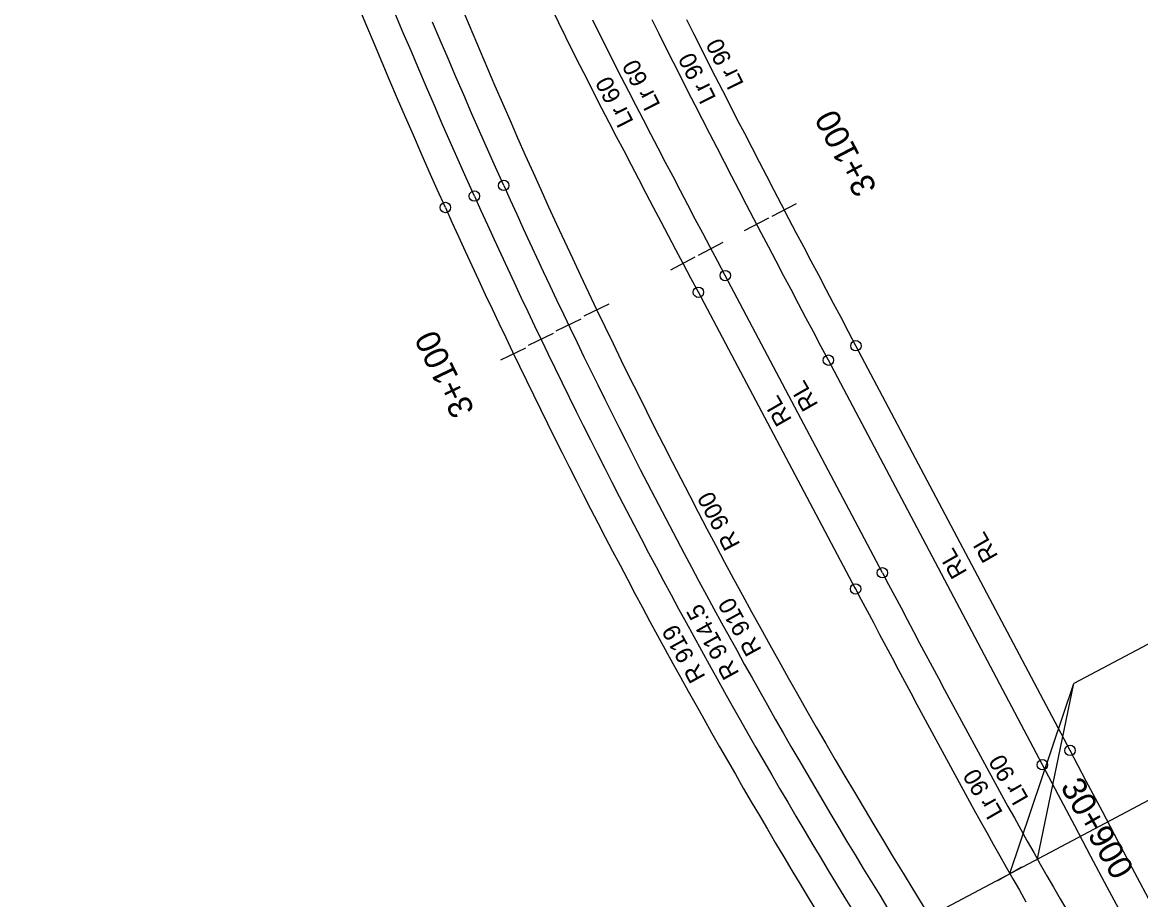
# Model space of a CAD drawing. Extents: x 149855 to 151460, y 6580726 to 6583068.
# Drawn here: x 150982.7 to 151144.3, y 6581306.4 to 6581433.2 of the extents above; entities that cross this region are included whole.
import ezdxf

# ---------------------------------------------------------------- set-up
doc = ezdxf.new("R2010")
doc.units = 0
for name, color, linetype in [('Hektometer L', 7, 'Continuous'), ('Hektometer T', 7, 'Continuous'), ('Konnektion längdmätning L', 7, 'Continuous'), ('Spårgeometri T', 7, 'Continuous'), ('Spårmitt L', 7, 'Continuous'), ('Tp bef behålls P', 7, 'Continuous')]:
    doc.layers.add(name, color=color, linetype=linetype)

msp = doc.modelspace()

# ---------------------------------------------------------------- linework, layer by layer
at = {"layer": 'Hektometer L'}
for points in [[(151091.04, 6581405.14), (151094.59, 6581406.99)], [(151087.05, 6581403.07), (151090.6, 6581404.92)], [(151080.44, 6581399.55), (151083.98, 6581401.42)], [(151076.42, 6581397.42), (151079.96, 6581399.29)], [(151063.91, 6581390.78), (151067.52, 6581392.51)], [(151059.84, 6581388.61), (151063.45, 6581390.35)], [(151055.85, 6581386.55), (151059.46, 6581388.28)], [(151051.88, 6581384.42), (151055.49, 6581386.15)], [(151123.66, 6581309.21), (151127.14, 6581311.18)]]:
    msp.add_lwpolyline(points, dxfattribs=at)
at = {"layer": 'Konnektion längdmätning L'}
for p, q in [((150982.75, 6581234.65), (151228.43, 6581364.77)), ((151125.39, 6581310.2), (151134.66, 6581337.65)), ((151129.38, 6581312.32), (151134.66, 6581337.65))]:
    msp.add_line(p, q, dxfattribs=at)
msp.add_lwpolyline([(151223.03, 6581384.46), (151134.66, 6581337.65)], dxfattribs=at)
at = {"layer": 'Spårmitt L'}
for points in [[(151043.85, 6581406.41), (151042.69, 6581409.01), (151041.53, 6581411.62), (151040.37, 6581414.24), (151039.23, 6581416.85), (151038.09, 6581419.48), (151036.95, 6581422.1), (151035.83, 6581424.72), (151034.71, 6581427.35), (151033.6, 6581429.98), (151032.49, 6581432.62), (151031.38, 6581435.25)], [(151048.04, 6581408.07), (151046.87, 6581410.68), (151045.71, 6581413.29), (151044.56, 6581415.91), (151043.41, 6581418.52), (151042.27, 6581421.14), (151041.14, 6581423.77), (151040.01, 6581426.39), (151038.89, 6581429.02), (151037.78, 6581431.65), (151036.67, 6581434.28)], [(151080.41, 6581394.16), (151079.33, 6581396.2), (151078.25, 6581398.24), (151077.17, 6581400.28), (151076.09, 6581402.32), (151075.02, 6581404.36), (151073.94, 6581406.4), (151072.87, 6581408.44), (151071.79, 6581410.48), (151070.72, 6581412.53), (151069.66, 6581414.58), (151068.59, 6581416.62), (151067.53, 6581418.67), (151066.48, 6581420.72), (151065.42, 6581422.78), (151064.38, 6581424.83), (151063.33, 6581426.89), (151062.29, 6581428.95), (151061.26, 6581431.02), (151060.23, 6581433.08), (151059.21, 6581435.15)], [(151052.28, 6581409.61), (151051.11, 6581412.22), (151049.95, 6581414.83), (151048.79, 6581417.44), (151047.64, 6581420.06), (151046.5, 6581422.68), (151045.37, 6581425.3), (151044.25, 6581427.93), (151043.12, 6581430.56), (151042.01, 6581433.19)], [(151084.28, 6581396.58), (151083.2, 6581398.62), (151082.12, 6581400.66), (151081.04, 6581402.7), (151079.96, 6581404.74), (151078.89, 6581406.78), (151077.81, 6581408.83), (151076.74, 6581410.87), (151075.67, 6581412.91), (151074.6, 6581414.96), (151073.53, 6581417.01), (151072.47, 6581419.05), (151071.41, 6581421.1), (151070.36, 6581423.16), (151069.3, 6581425.21), (151068.26, 6581427.27), (151067.21, 6581429.33), (151066.18, 6581431.39), (151065.14, 6581433.45)], [(151099.18, 6581384.36), (151098.1, 6581386.4), (151097.02, 6581388.44), (151095.94, 6581390.48), (151094.86, 6581392.52), (151093.79, 6581394.56), (151092.71, 6581396.6), (151091.63, 6581398.64), (151090.56, 6581400.69), (151089.49, 6581402.73), (151088.42, 6581404.77), (151087.35, 6581406.82), (151086.28, 6581408.87), (151085.22, 6581410.91), (151084.16, 6581412.96), (151083.1, 6581415.01), (151082.04, 6581417.06), (151080.99, 6581419.12), (151079.94, 6581421.17), (151078.89, 6581423.23), (151077.85, 6581425.29), (151076.81, 6581427.35), (151075.77, 6581429.41), (151074.74, 6581431.48), (151073.72, 6581433.54)], [(151103.17, 6581386.42), (151102.09, 6581388.46), (151101.01, 6581390.5), (151099.93, 6581392.54), (151098.86, 6581394.58), (151097.78, 6581396.62), (151096.7, 6581398.66), (151095.63, 6581400.71), (151094.55, 6581402.75), (151093.48, 6581404.79), (151092.41, 6581406.84), (151091.34, 6581408.88), (151090.27, 6581410.93), (151089.21, 6581412.98), (151088.15, 6581415.03), (151087.09, 6581417.08), (151086.03, 6581419.13), (151084.98, 6581421.18), (151083.93, 6581423.24), (151082.88, 6581425.29), (151081.84, 6581427.35), (151080.8, 6581429.41), (151079.77, 6581431.48), (151078.74, 6581433.54)], [(151106.99, 6581353.65), (151084.28, 6581396.58)], [(151103.11, 6581351.31), (151080.41, 6581394.16)], [(151134.09, 6581327.99), (151103.17, 6581386.42)], [(151130.1, 6581325.93), (151099.18, 6581384.36)], [(151106.99, 6581353.65), (151107.89, 6581351.96), (151108.79, 6581350.26), (151109.68, 6581348.57), (151110.58, 6581346.88), (151111.48, 6581345.19), (151112.37, 6581343.5), (151113.27, 6581341.81), (151114.17, 6581340.12), (151115.08, 6581338.43), (151115.98, 6581336.74), (151116.88, 6581335.05), (151117.79, 6581333.36), (151118.7, 6581331.68), (151119.61, 6581329.99), (151120.52, 6581328.31), (151121.44, 6581326.63), (151122.35, 6581324.95), (151123.27, 6581323.27), (151124.2, 6581321.59), (151125.12, 6581319.91), (151126.05, 6581318.24), (151126.98, 6581316.57), (151127.92, 6581314.9), (151128.86, 6581313.23), (151129.8, 6581311.56), (151130.75, 6581309.9), (151131.7, 6581308.24), (151132.66, 6581306.58), (151133.62, 6581304.92)], [(151102.99, 6581351.53), (151103.89, 6581349.84), (151104.78, 6581348.14), (151105.68, 6581346.45), (151106.58, 6581344.76), (151107.48, 6581343.07), (151108.38, 6581341.38), (151109.28, 6581339.69), (151110.18, 6581338), (151111.08, 6581336.31), (151111.98, 6581334.62), (151112.89, 6581332.93), (151113.8, 6581331.25), (151114.7, 6581329.56), (151115.62, 6581327.88), (151116.53, 6581326.19), (151117.44, 6581324.51), (151118.36, 6581322.83), (151119.28, 6581321.15), (151120.21, 6581319.48), (151121.13, 6581317.8), (151122.06, 6581316.13), (151123, 6581314.45), (151123.93, 6581312.78), (151124.87, 6581311.12), (151125.82, 6581309.45), (151126.77, 6581307.79), (151127.72, 6581306.13)], [(151167.13, 6581266.28), (151164.73, 6581270.66), (151162.34, 6581275.06), (151159.96, 6581279.45), (151157.59, 6581283.85), (151155.22, 6581288.26), (151152.86, 6581292.66), (151150.5, 6581297.07), (151148.15, 6581301.48), (151145.8, 6581305.9), (151143.45, 6581310.31), (151141.11, 6581314.73), (151138.77, 6581319.15), (151136.43, 6581323.57), (151134.09, 6581327.99)], [(151163.13, 6581264.21), (151160.73, 6581268.6), (151158.35, 6581272.99), (151155.96, 6581277.39), (151153.59, 6581281.79), (151151.22, 6581286.19), (151148.86, 6581290.6), (151146.5, 6581295.01), (151144.15, 6581299.42), (151141.8, 6581303.84), (151139.46, 6581308.25), (151137.12, 6581312.67), (151134.78, 6581317.09), (151132.44, 6581321.51), (151130.1, 6581325.93)]]:
    msp.add_lwpolyline(points, dxfattribs=at)
for centre, radius, start, end in [((151877.46, 6581780.33), 900, 202.28355, 213.39793), ((151881.95, 6581783.43), 910, 204.25457, 213.42998), ((151881.9, 6581783.56), 914.5, 204.24219, 213.43976), ((151881.9, 6581783.56), 919, 204.22992, 213.40688)]:
    msp.add_arc(centre, radius, start, end, dxfattribs=at)
at = {"layer": 'Tp bef behålls P'}
for centre in [(151052.28, 6581409.61), (151048.04, 6581408.07), (151043.85, 6581406.41), (151084.28, 6581396.58), (151080.41, 6581394.16), (151103.16, 6581386.44), (151099.18, 6581384.36), (151106.99, 6581353.65), (151103.11, 6581351.31), (151134.09, 6581327.99), (151130.1, 6581325.93)]:
    msp.add_circle(centre, 0.75, dxfattribs=at)

# ---------------------------------------------------------------- texts
at = {"layer": 'Hektometer T'}
for s, rotation, p in [('3+100', 117.6354, (151106.27, 6581409.22)), ('3+100', 115.6527, (151048.13, 6581377.13)), ('30+900', 299.6069, (151132.63, 6581322.76))]:
    msp.add_text(s, height=3.5, rotation=rotation, dxfattribs=at).set_placement(p)
at = {"layer": 'Spårgeometri T'}
for s, rotation, p in [('Lr 90', 116.5115, (151087.02, 6581424.28)), ('Lr 60', 116.9244, (151074.97, 6581421.24)), ('Lr 90', 116.5197, (151083.02, 6581422.21)), ('Lr 60', 116.9619, (151071.1, 6581418.81)), ('RL', 119.9014, (151097.78, 6581377.92)), ('RL', 119.9014, (151093.98, 6581375.76)), ('R 900', 117.8407, (151086.51, 6581357.74)), ('RL', 119.9014, (151123.78, 6581356.06)), ('RL', 119.9014, (151119.3, 6581353.73)), ('R 910', 118.8423, (151089.61, 6581342.51)), ('R 914.5', 118.841, (151086.36, 6581339.12)), ('R 919', 118.8184, (151081.5, 6581338.62)), ('Lr 90', 119.9014, (151128.18, 6581321.06)), ('Lr 90', 119.9106, (151124.46, 6581319))]:
    msp.add_text(s, height=2.5, rotation=rotation, dxfattribs=at).set_placement(p)

doc.saveas('drawing.dxf')
